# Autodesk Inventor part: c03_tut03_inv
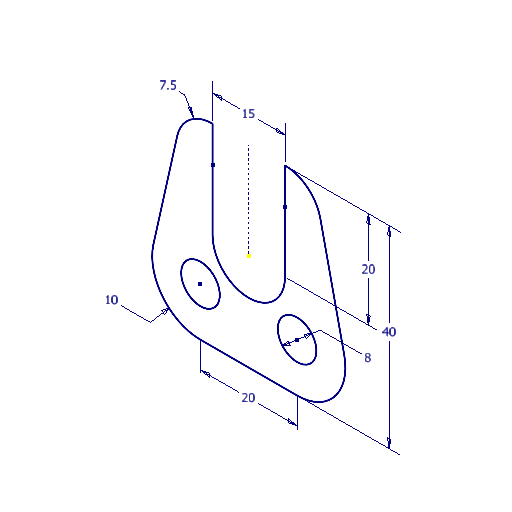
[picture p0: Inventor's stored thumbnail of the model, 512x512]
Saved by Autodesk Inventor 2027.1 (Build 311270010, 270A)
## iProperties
Created: 2017-04
Part Number: c03_tut03_inv
Material: Generic
Document SubType Name: Modeling
Designer: CADCIM 00
Density: 1 g/cm^3
Appearance: Default
Author: CADCIM 00
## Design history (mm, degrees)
sketch "Sketch1"
  geometry: L1 (-10, -20)-(10, -20); L2 (19.756, -7.805)-(14.817, 14.146); L3 (7.5, 20)-(7.5, 0); L4 (-7.5, 0)-(-7.5, 20); L5 (-14.817, 14.146)-(-19.756, -7.805); L6 (0, 0)-(0, 20); C1 r 4 at (-10, -10); C2 r 4 at (10, -10); A1 r 10 centre (10, -10) between (10, -20) and (19.756, -7.805); A2 r 7.5 centre (7.5, 12.5) between (14.817, 14.146) and (7.5, 20); A3 r 7.5 centre (0, 0) between (-7.5, 0) and (7.5, 0); A4 r 7.5 centre (-7.5, 12.5) between (-7.5, 20) and (-14.817, 14.146); A5 r 10 centre (-10, -10) between (-19.756, -7.805) and (-10, -20); 1 further point
  constraints: 12 end point, 10 point on circle, 8 tangent, 7 centre point, 3 coincident, 3 equal radius, 2 equal length, 2 point on line, 1 horizontal, 1 horizontal alignment, 1 parallel, 1 perpendicular, 1 vertical, 3 other
  dimensions: "d0" = 20 distance of L1.start L1.end; "d1" = 7.5 radius of A2; "d2" = 10 radius of A1; "d3" = 15 distance between parallel lines of L4 L3; "d5" = 40 distance from line of L1 L4.end; "d6" = 20 distance of L4.start L4.end; "d7" = 8 diameter of C1
